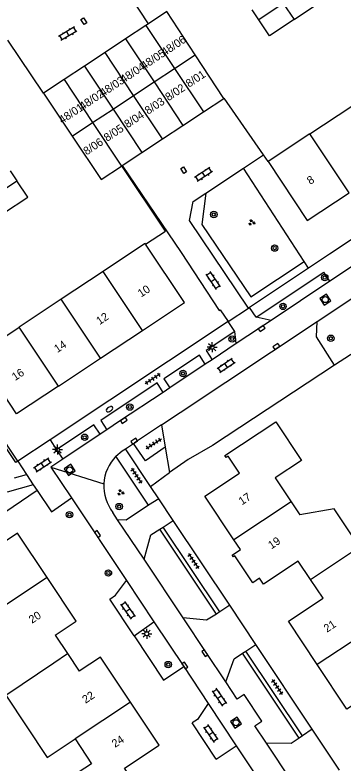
# Model space of a CAD drawing. Extents: x 137999 to 141000, y 397500 to 400501.
# Drawn here: x 138297 to 138337.9, y 399575 to 399668.5 of the extents above; entities that cross this region are included whole.
import ezdxf

# ---------------------------------------------------------------- set-up
doc = ezdxf.new("R2010")
doc.units = 0
for name, color, linetype in [('gg-afsc-erfafscheiding', 7, 'Continuous'), ('gg-anno-huisnummerreeks BGT', 7, 'Continuous'), ('gg-bbg-bijgebouw', 7, 'Continuous'), ('gg-bbg-gedigitaliseerde bebouwing', 7, 'Continuous'), ('gg-bbg-gedigitaliseerde bijgebouw', 7, 'Continuous'), ('gg-bbg-hoofdgebouw', 7, 'Continuous'), ('gg-bbg-tussenscheiding', 7, 'Continuous'), ('gg-knt-verharding', 7, 'Continuous'), ('gg-knt-verharding nz', 7, 'Continuous'), ('gt-grn-groengrens', 7, 'Continuous'), ('gt-grn-weggrens', 7, 'Continuous'), ('gt-symb-boom', 7, 'Continuous'), ('gt-symb-brandkraan', 7, 'Continuous'), ('gt-symb-groenvak', 7, 'Continuous'), ('gt-symb-klinker verharding', 7, 'Continuous'), ('gt-symb-kolk', 7, 'Continuous'), ('gt-symb-kolk center center', 7, 'Continuous'), ('gt-symb-lichtmast', 7, 'Continuous'), ('gt-symb-rioolschacht', 7, 'Continuous'), ('gt-symb-tegel verharding', 7, 'Continuous')]:
    doc.layers.add(name, color=color, linetype=linetype)

# ---------------------------------------------------------------- blocks, each defined once
blk = doc.blocks.new('gt0-RS')
at = {"layer": 'gt-symb-rioolschacht'}
blk.add_lwpolyline([(-0.5, -0.5), (0.5, -0.5), (0.5, 0.5), (-0.5, 0.5)], close=True, dxfattribs=at)
blk.add_circle((0, 0), 0.375, dxfattribs=at)
blk = doc.blocks.new('gt0-KL1')
at = {"layer": 'gt-symb-klinker verharding'}
for p, q in [((-1.15, 0.3), (1.15, 0.3)), ((-1, -0.3), (-1, 0.3)), ((-0.5, 0.3), (-0.5, 0.45)), ((0, -0.3), (0, 0.3)), ((0.5, 0.3), (0.5, 0.45)), ((1, -0.3), (1, 0.3)), ((-1.15, -0.3), (1.15, -0.3)), ((-0.5, -0.45), (-0.5, -0.3)), ((0.5, -0.45), (0.5, -0.3))]:
    blk.add_line(p, q, dxfattribs=at)
blk = doc.blocks.new('gt0-LMAST')
at = {"layer": 'gt-symb-lichtmast'}
for p, q in [((-0.182, 0.173), (-0.447, 0.438)), ((-0.005, 0.246), (-0.005, 0.621)), ((0.172, 0.173), (0.437, 0.438)), ((-0.255, -0.004), (-0.63, -0.004)), ((-0.182, -0.181), (-0.447, -0.446)), ((-0.005, -0.254), (-0.005, -0.629)), ((0.437, -0.446), (0.172, -0.181)), ((0.245, -0.004), (0.62, -0.004))]:
    blk.add_line(p, q, dxfattribs=at)
blk.add_circle((-0.005, -0.004), 0.25, dxfattribs=at)
blk = doc.blocks.new('gt0-BOOM')
at = {"layer": 'gt-symb-boom'}
for radius in [0.4, 0.2]:
    blk.add_circle((0, 0), radius, dxfattribs=at)
blk = doc.blocks.new('gt0-TEG1')
at = {"layer": 'gt-symb-tegel verharding'}
for p, q in [((-1.125, 0), (1.125, 0)), ((-0.9, -0.25), (-0.9, 0.25)), ((-0.45, -0.25), (-0.45, 0.25)), ((0, -0.25), (0, 0.25)), ((0.45, -0.25), (0.45, 0.25)), ((0.9, -0.25), (0.9, 0.25))]:
    blk.add_line(p, q, dxfattribs=at)
blk = doc.blocks.new('gt0-KOLK')
at = {"layer": 'gt-symb-kolk'}
blk.add_lwpolyline([(0, 0), (0.375, 0), (0.375, 0.4), (-0.375, 0.4), (-0.375, 0), (0, 0)], dxfattribs=at)
blk = doc.blocks.new('gt0-KOLKCC')
at = {"layer": 'gt-symb-kolk center center'}
blk.add_lwpolyline([(-0.375, 0.2), (0.375, 0.2), (0.375, -0.2), (-0.375, -0.2)], close=True, dxfattribs=at)
blk = doc.blocks.new('gt0-GRVAK')
at = {"layer": 'gt-symb-groenvak'}
for p, q in [((-0.11, 0.189), (-0.228, 0.24)), ((-0.182, 0.153), (0.088, 0.153)), ((-0.091, 0.211), (-0.156, 0.322)), ((-0.047, 0.214), (-0.047, 0.393)), ((-0.004, 0.211), (0.061, 0.322)), ((0.015, 0.189), (0.133, 0.24)), ((0.262, -0.052), (0.197, 0.059)), ((0.305, -0.049), (0.305, 0.13)), ((0.349, -0.052), (0.414, 0.059)), ((-0.245, -0.228), (-0.363, -0.177)), ((-0.318, -0.264), (-0.047, -0.264)), ((-0.226, -0.206), (-0.291, -0.095)), ((-0.183, -0.203), (-0.183, -0.024)), ((-0.139, -0.206), (-0.074, -0.095)), ((-0.12, -0.228), (-0.002, -0.177)), ((0.243, -0.074), (0.125, -0.023)), ((0.17, -0.11), (0.441, -0.11)), ((0.368, -0.074), (0.486, -0.023))]:
    blk.add_line(p, q, dxfattribs=at)
blk = doc.blocks.new('gt0-BR')
at = {"layer": 'gt-symb-brandkraan'}
for centre, radius, start, end in [((-0.244, 0), 0.206, 107.56694, 252.43307), ((0.599, -2.664), 3, 106.89205, 107.56694), ((0, -0.691), 0.938, 73.10799, 106.89205), ((-0.599, -2.664), 3, 72.43309, 73.10799), ((0.244, 0), 0.206, 287.56695, 72.43309), ((0.599, 2.664), 3, 252.43307, 253.10797), ((0, 0.691), 0.938, 253.10797, 286.89206), ((-0.599, 2.664), 3, 286.89206, 287.56695)]:
    blk.add_arc(centre, radius, start, end, dxfattribs=at)

msp = doc.modelspace()

# ---------------------------------------------------------------- linework, layer by layer
at = {"layer": 'gg-afsc-erfafscheiding'}
for p, q in [((138313.661, 399667.342), (138308.575, 399675.225)), ((138327.43, 399667.857), (138326.596, 399669.102)), ((138300.604, 399658.7), (138296.142, 399665.293)), ((138328.58, 399650.16), (138328.018, 399650.974)), ((138296.438, 399648.991), (138297.27, 399647.743)), ((138297.402, 399612.731), (138284.82, 399631.59)), ((138343.575, 399629.136), (138336.884, 399624.719)), ((138299.793, 399609.056), (138291.36, 399603.341)), ((138322.132, 399575.534), (138319.133, 399580.038))]:
    msp.add_line(p, q, dxfattribs=at)
for points in [[(138328.018, 399650.974), (138323.122, 399658.068), (138323.073, 399658.036)], [(138313.32, 399639.82), (138315.806, 399641.472), (138310.366, 399649.617)]]:
    msp.add_lwpolyline(points, dxfattribs=at)
at = {"layer": 'gg-bbg-bijgebouw'}
for p, q in [((138313.365, 399667.146), (138310.811, 399665.456)), ((138313.661, 399667.342), (138313.365, 399667.146)), ((138310.811, 399665.456), (138308.26, 399663.768)), ((138308.26, 399663.768), (138305.706, 399662.077)), ((138323.073, 399658.036), (138319.498, 399663.487)), ((138305.706, 399662.077), (138303.153, 399660.387)), ((138303.153, 399660.387), (138300.604, 399658.7)), ((138300.604, 399658.7), (138304.162, 399653.327)), ((138320.521, 399656.345), (138323.073, 399658.036)), ((138317.969, 399654.654), (138320.521, 399656.345)), ((138315.418, 399652.964), (138317.969, 399654.654)), ((138304.162, 399653.327), (138307.761, 399647.891)), ((138312.864, 399651.272), (138315.418, 399652.964)), ((138310.417, 399649.651), (138312.864, 399651.272)), ((138307.761, 399647.891), (138310.312, 399649.581)), ((138310.312, 399649.581), (138310.366, 399649.617)), ((138310.366, 399649.617), (138310.417, 399649.651))]:
    msp.add_line(p, q, dxfattribs=at)
msp.add_lwpolyline([(138319.498, 399663.487), (138315.968, 399668.869), (138313.661, 399667.342)], dxfattribs=at)
at = {"layer": 'gg-bbg-gedigitaliseerde bebouwing'}
for p, q in [((138331.476, 399607.641), (138332.54, 399606.04)), ((138336.822, 399606.758), (138332.54, 399606.04)), ((138339.978, 399602.034), (138336.822, 399606.758)), ((138302.038, 399591), (138303.583, 399588.699)), ((138303.583, 399588.699), (138305.056, 399586.505))]:
    msp.add_line(p, q, dxfattribs=at)
for points in [[(138329.55, 399617.651), (138332.765, 399612.821), (138329.483, 399610.638), (138331.476, 399607.641)], [(138295.875, 399583.524), (138301.048, 399575.724), (138304.527, 399578.045)], [(138304.527, 399578.045), (138306.581, 399574.947), (138303.143, 399572.668), (138306.226, 399568.018)]]:
    msp.add_lwpolyline(points, dxfattribs=at)
at = {"layer": 'gg-bbg-gedigitaliseerde bijgebouw'}
for p, q in [((138330.475, 399669.888), (138327.43, 399667.857)), ((138294.239, 399645.721), (138297.27, 399647.743))]:
    msp.add_line(p, q, dxfattribs=at)
for points in [[(138331.817, 399667.88), (138334.86, 399669.91), (138333.52, 399671.92)], [(138331.817, 399667.88), (138328.773, 399665.849), (138327.43, 399667.857)], [(138295.594, 399643.688), (138298.626, 399645.711), (138297.27, 399647.743)]]:
    msp.add_lwpolyline(points, dxfattribs=at)
at = {"layer": 'gg-bbg-hoofdgebouw'}
for p, q in [((138333.804, 399653.62), (138339.032, 399657.081)), ((138333.804, 399653.62), (138328.58, 399650.16)), ((138328.58, 399650.16), (138333.47, 399642.78)), ((138333.47, 399642.78), (138338.695, 399646.245)), ((138313.185, 399639.86), (138308.022, 399636.431)), ((138308.022, 399636.431), (138302.791, 399632.956)), ((138302.791, 399632.956), (138297.559, 399629.48)), ((138307.684, 399625.584), (138312.917, 399629.057)), ((138302.451, 399622.111), (138307.684, 399625.584)), ((138325.127, 399601.698), (138324.321, 399602.906))]:
    msp.add_line(p, q, dxfattribs=at)
for points in [[(138312.917, 399629.057), (138318.15, 399632.53), (138313.32, 399639.82)], [(138313.32, 399639.82), (138313.26, 399639.91), (138313.185, 399639.86)], [(138302.451, 399622.111), (138297.22, 399618.64), (138292.35, 399626.02), (138297.559, 399629.48)], [(138324.321, 399602.906), (138320.69, 399608.35), (138325.01, 399611.24), (138323.59, 399613.37), (138323.34, 399613.2), (138323.2, 399613.42), (138329.55, 399617.651)], [(138301.037, 399598.217), (138297.36, 399603.74), (138293.03, 399600.85), (138291.36, 399603.341)], [(138327.524, 399598.103), (138326.677, 399597.538), (138324.441, 399600.89), (138324.257, 399600.767), (138324.094, 399601.009), (138325.127, 399601.698)], [(138333.874, 399597.957), (138332.35, 399600.24), (138328.02, 399597.36), (138327.524, 399598.103)], [(138302.038, 399591), (138304.67, 399592.76), (138301.037, 399598.217)], [(138334.69, 399587.345), (138331.11, 399592.73), (138335.44, 399595.61), (138333.874, 399597.957)], [(138311.427, 399582.648), (138307.68, 399588.26), (138305.056, 399586.505)], [(138344.312, 399582.284), (138342.74, 399584.63), (138338.41, 399581.75), (138334.69, 399587.345)], [(138312.256, 399572.027), (138310.69, 399574.39), (138315.01, 399577.28), (138311.427, 399582.648)]]:
    msp.add_lwpolyline(points, dxfattribs=at)
at = {"layer": 'gg-bbg-tussenscheiding'}
for p, q in [((138330.475, 399669.888), (138331.817, 399667.88)), ((138313.365, 399667.146), (138316.921, 399661.779)), ((138310.811, 399665.456), (138314.368, 399660.088)), ((138311.818, 399658.398), (138308.26, 399663.768)), ((138316.921, 399661.779), (138319.498, 399663.487)), ((138305.706, 399662.077), (138309.264, 399656.706)), ((138314.368, 399660.088), (138316.921, 399661.779)), ((138316.921, 399661.779), (138320.521, 399656.345)), ((138303.153, 399660.387), (138306.711, 399655.016)), ((138311.818, 399658.398), (138314.368, 399660.088)), ((138314.368, 399660.088), (138317.969, 399654.654)), ((138309.264, 399656.706), (138311.818, 399658.398)), ((138315.418, 399652.964), (138311.818, 399658.398)), ((138306.711, 399655.016), (138309.264, 399656.706)), ((138309.264, 399656.706), (138312.864, 399651.272)), ((138304.162, 399653.327), (138306.711, 399655.016)), ((138306.711, 399655.016), (138310.312, 399649.581)), ((138338.695, 399646.245), (138333.804, 399653.62)), ((138312.917, 399629.057), (138308.022, 399636.431)), ((138307.684, 399625.584), (138302.791, 399632.956)), ((138302.451, 399622.111), (138297.559, 399629.48)), ((138331.476, 399607.641), (138324.321, 399602.906)), ((138333.874, 399597.957), (138339.978, 399602.034)), ((138301.037, 399598.217), (138294.121, 399593.592)), ((138341.729, 399591.976), (138334.69, 399587.345)), ((138301.893, 399587.564), (138303.583, 399588.699)), ((138295.875, 399583.524), (138301.893, 399587.564)), ((138311.427, 399582.648), (138304.527, 399578.045))]:
    msp.add_line(p, q, dxfattribs=at)
at = {"layer": 'gg-knt-verharding'}
for p, q in [((138325.505, 399649.302), (138328.018, 399650.974)), ((138310.417, 399649.651), (138317.731, 399638.79)), ((138320.833, 399646.194), (138325.505, 399649.302)), ((138333.066, 399637.651), (138325.505, 399649.302)), ((138319.247, 399645.139), (138320.833, 399646.194)), ((138318.789, 399642.787), (138319.247, 399645.139)), ((138326.151, 399631.856), (138318.789, 399642.787)), ((138333.608, 399636.816), (138333.066, 399637.651)), ((138333.608, 399636.816), (138326.26, 399631.928)), ((138339.112, 399637.078), (138336.29, 399635.195)), ((138327.109, 399630.7), (138335.537, 399636.323)), ((138336.29, 399635.195), (138335.537, 399636.323)), ((138336.29, 399635.195), (138328.951, 399630.299)), ((138334.711, 399630.191), (138340.363, 399633.957)), ((138326.26, 399631.928), (138326.151, 399631.856)), ((138327.109, 399630.7), (138326.26, 399631.928)), ((138323.614, 399630.168), (138301.412, 399615.399)), ((138324.45, 399628.908), (138323.614, 399630.168)), ((138328.951, 399630.299), (138324.614, 399627.406)), ((138328.951, 399630.299), (138327.109, 399630.7)), ((138324.614, 399627.406), (138324.45, 399628.908)), ((138324.614, 399627.406), (138321.609, 399625.402)), ((138320.748, 399624.827), (138316.329, 399621.879)), ((138321.609, 399625.402), (138320.748, 399624.827)), ((138316.329, 399621.879), (138315.491, 399621.32)), ((138315.491, 399621.32), (138310.078, 399617.709)), ((138310.078, 399617.709), (138308.484, 399616.646)), ((138315.303, 399617.266), (138311.916, 399615.009)), ((138315.303, 399617.266), (138315.771, 399614.478)), ((138307.648, 399616.088), (138302.983, 399612.976)), ((138308.484, 399616.646), (138307.648, 399616.088)), ((138301.412, 399615.399), (138297.402, 399612.731)), ((138301.412, 399615.399), (138302.219, 399614.155)), ((138310.807, 399614.271), (138311.799, 399614.931)), ((138313.94, 399609.561), (138310.807, 399614.271)), ((138311.799, 399614.931), (138311.916, 399615.009)), ((138315.771, 399614.478), (138316.299, 399611.331)), ((138302.219, 399614.155), (138302.983, 399612.976)), ((138313.697, 399607.215), (138309.618, 399613.342)), ((138297.402, 399612.731), (138298.47, 399611.077)), ((138302.983, 399612.976), (138301.52, 399612)), ((138301.52, 399612), (138304.088, 399608.132)), ((138298.47, 399611.077), (138299.32, 399609.76)), ((138299.32, 399609.76), (138296.061, 399608.844)), ((138299.32, 399609.76), (138299.793, 399609.056)), ((138314.956, 399608.033), (138313.94, 399609.561)), ((138304.088, 399608.132), (138310.92, 399597.84)), ((138314.956, 399608.033), (138313.697, 399607.215)), ((138316.76, 399605.322), (138314.956, 399608.033)), ((138309.824, 399605.403), (138309.24, 399606.33)), ((138315.504, 399604.498), (138316.76, 399605.322)), ((138323.802, 399594.735), (138316.76, 399605.322)), ((138315.086, 399604.223), (138315.504, 399604.498)), ((138322.559, 399593.899), (138315.504, 399604.498)), ((138317.996, 399593.149), (138313.127, 399600.492)), ((138310.92, 399597.84), (138314.343, 399592.684)), ((138323.802, 399594.735), (138322.559, 399593.899)), ((138327.06, 399589.836), (138323.802, 399594.735)), ((138322.317, 399593.736), (138322.144, 399593.62)), ((138322.559, 399593.899), (138322.317, 399593.736)), ((138311.894, 399590.908), (138314.343, 399592.684)), ((138314.343, 399592.684), (138318.069, 399587.071)), ((138325.395, 399588.737), (138325.812, 399589.012)), ((138325.812, 399589.012), (138327.06, 399589.836)), ((138332.855, 399578.43), (138325.812, 399589.012)), ((138334.091, 399579.266), (138327.06, 399589.836)), ((138318.069, 399587.071), (138321.137, 399582.449)), ((138321.137, 399582.449), (138324.622, 399577.2)), ((138334.091, 399579.266), (138332.855, 399578.43)), ((138337.49, 399574.155), (138334.091, 399579.266)), ((138332.855, 399578.43), (138332.441, 399578.15)), ((138322.132, 399575.534), (138324.622, 399577.2)), ((138324.622, 399577.2), (138331.691, 399566.551))]:
    msp.add_line(p, q, dxfattribs=at)
for points in [[(138357.133, 399652.465), (138336.262, 399638.582), (138333.608, 399636.816)], [(138297.402, 399612.731), (138297.16, 399612.57), (138284.58, 399631.42), (138284.82, 399631.59)], [(138322.501, 399631.546), (138322.632, 399631.633), (138323.614, 399630.168)], [(138336.884, 399624.719), (138334.635, 399628.241), (138334.711, 399630.191)], [(138324.45, 399628.908), (138320.868, 399626.531), (138321.609, 399625.402)], [(138320.748, 399624.827), (138320.028, 399625.965), (138315.581, 399623.02), (138316.329, 399621.879)], [(138336.884, 399624.719), (138321.672, 399614.675), (138318.628, 399612.937), (138316.299, 399611.331)], [(138315.491, 399621.32), (138314.77, 399622.493), (138307.722, 399617.814), (138308.484, 399616.646)], [(138307.648, 399616.088), (138306.863, 399617.282), (138302.219, 399614.155)], [(138309.618, 399613.342), (138310.399, 399614), (138310.807, 399614.271)], [(138315.771, 399614.478), (138313.319, 399612.76), (138311.799, 399614.931)], [(138299.793, 399609.056), (138301.57, 399606.41), (138304.088, 399608.132)], [(138313.697, 399607.215), (138310.894, 399605.363), (138309.824, 399605.403)], [(138313.127, 399600.492), (138313.973, 399603.518), (138315.086, 399604.223)], [(138311.894, 399590.908), (138308.84, 399595.494), (138309.56, 399596.003), (138310.92, 399597.84)], [(138322.144, 399593.62), (138320.908, 399592.859), (138317.996, 399593.149)], [(138323.319, 399585.169), (138324.341, 399588.055), (138325.395, 399588.737)], [(138328.375, 399577.523), (138326.938, 399579.682), (138327.797, 399580.262), (138325.591, 399583.606), (138324.718, 399583.019), (138323.319, 399585.169)], [(138321.137, 399582.449), (138319.797, 399580.482), (138319.133, 399580.038)], [(138332.441, 399578.15), (138331.447, 399577.459), (138328.375, 399577.523)]]:
    msp.add_lwpolyline(points, dxfattribs=at)
for centre, radius, start, end in [((138313.418, 399609.62), 5.319, 135.60054, 176.91165), ((138313.417, 399609.621), 5.318, 176.91816, 218.23261)]:
    msp.add_arc(centre, radius, start, end, dxfattribs=at)
at = {"layer": 'gg-knt-verharding nz'}
for p, q in [((138317.731, 399638.79), (138322.501, 399631.546)), ((138317.608, 399618.801), (138334.711, 399630.191)), ((138315.303, 399617.266), (138317.608, 399618.801)), ((138313.127, 399600.492), (138309.824, 399605.403)), ((138333.776, 399569.384), (138328.375, 399577.523))]:
    msp.add_line(p, q, dxfattribs=at)
msp.add_lwpolyline([(138323.319, 399585.169), (138320.853, 399588.855), (138317.996, 399593.149)], dxfattribs=at)
at = {"layer": 'gt-grn-groengrens'}
for p, q in [((138313.94, 399609.561), (138316.299, 399611.331)), ((138322.144, 399593.62), (138315.086, 399604.223)), ((138332.441, 399578.15), (138325.395, 399588.737))]:
    msp.add_line(p, q, dxfattribs=at)
for points in [[(138320.833, 399646.194), (138320.333, 399642.285), (138326.425, 399633.239), (138333.066, 399637.651)], [(138311.894, 399590.908), (138315.561, 399585.401), (138318.069, 399587.071)]]:
    msp.add_lwpolyline(points, dxfattribs=at)
at = {"layer": 'gt-grn-weggrens'}
for p, q in [((138323.614, 399630.168), (138326.151, 399631.856)), ((138301.52, 399612), (138308.107, 399609.907)), ((138296.97, 399610.65), (138298.47, 399611.077))]:
    msp.add_line(p, q, dxfattribs=at)

# ---------------------------------------------------------------- block references
at = {"layer": 'gt-symb-boom'}
for p in [(138321.819, 399643.53), (138329.405, 399639.336), (138335.649, 399635.661), (138330.448, 399632.057), (138324.106, 399627.991), (138317.982, 399623.677), (138311.349, 399619.487), (138305.724, 399615.713), (138310.023, 399607.064), (138303.828, 399606.047), (138308.68, 399598.759), (138316.139, 399587.331)]:
    msp.add_blockref('gt0-BOOM', p, dxfattribs=at)
at = {"layer": 'gt-symb-boom', "rotation": 33.70595654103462}
msp.add_blockref('gt0-BOOM', (138336.41, 399628.078), dxfattribs=at)
at = {"layer": 'gt-symb-brandkraan', "rotation": -146.57996880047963}
msp.add_blockref('gt0-BR', (138308.812, 399619.209), dxfattribs=at)
at = {"layer": 'gt-symb-groenvak'}
for p in [(138326.537, 399642.534), (138310.2, 399608.817)]:
    msp.add_blockref('gt0-GRVAK', p, dxfattribs=at)
at = {"layer": 'gt-symb-klinker verharding'}
for p, rotation in [((138303.605, 399666.113), -149.20328608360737), ((138320.538, 399648.517), -146.91369260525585), ((138321.759, 399635.277), 123.83302869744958), ((138323.35, 399624.692), 34.532124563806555), ((138300.457, 399612.271), 33.83302869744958), ((138311.099, 399594.11), -55.18164551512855), ((138322.496, 399583.261), -55.46787543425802), ((138321.443, 399578.734), -55.46787543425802)]:
    msp.add_blockref('gt0-KL1', p, dxfattribs=dict(at, rotation=rotation))
at = {"layer": 'gt-symb-kolk'}
for p, rotation in [((138327.896, 399629.116), 33.78542795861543), ((138329.725, 399626.872), 33.785427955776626), ((138310.708, 399617.649), 33.785427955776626), ((138312.004, 399615.068), 33.78542795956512), ((138307.146, 399603.522), -56.42118627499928), ((138320.853, 399588.855), 123.79526709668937), ((138318.039, 399587.113), -56.42118627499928)]:
    msp.add_blockref('gt0-KOLK', p, dxfattribs=dict(at, rotation=rotation))
at = {"layer": 'gt-symb-kolk center center'}
for p, rotation in [((138305.629, 399667.685), -56.50059992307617), ((138318.064, 399649.072), 122.0053832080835)]:
    msp.add_blockref('gt0-KOLKCC', p, dxfattribs=dict(at, rotation=rotation))
at = {"layer": 'gt-symb-lichtmast'}
for p in [(138321.616, 399626.964), (138302.337, 399614.173), (138313.468, 399591.19)]:
    msp.add_blockref('gt0-LMAST', p, dxfattribs=at)
at = {"layer": 'gt-symb-rioolschacht'}
for p, rotation in [((138335.713, 399632.9), 33.78542795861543), ((138303.861, 399611.643), 33.78542795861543), ((138324.594, 399580.072), -56.42118627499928)]:
    msp.add_blockref('gt0-RS', p, dxfattribs=dict(at, rotation=rotation))
at = {"layer": 'gt-symb-tegel verharding'}
for p, rotation in [((138314.186, 399623.022), -146.5005999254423), ((138314.337, 399614.925), 31.798912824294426), ((138312.171, 399610.917), -56.500599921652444), ((138319.302, 399600.247), -56.50059992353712), ((138329.728, 399584.526), -56.500599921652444)]:
    msp.add_blockref('gt0-TEG1', p, dxfattribs=dict(at, rotation=rotation))

# ---------------------------------------------------------------- texts
at = {"layer": 'gg-anno-huisnummerreeks BGT'}
for s, rotation, p in [('48/06', 33.5, (138315.681, 399663.283)), ('48/05', 33.5, (138313.115, 399661.584)), ('48/04', 33.5, (138310.563, 399659.895)), ('8/01', 33.5, (138318.73, 399659.358)), ('48/03', 33.5, (138308.01, 399658.206)), ('48/02', 33.5, (138305.457, 399656.515)), ('8/02', 33.5, (138316.178, 399657.667)), ('8/03', 33.5, (138313.626, 399655.977)), ('48/01', 33.5, (138302.906, 399654.827)), ('8/04', 33.5, (138311.074, 399654.286)), ('8/05', 33.5, (138308.521, 399652.594)), ('8/06', 33.5, (138305.969, 399650.904)), ('8', 33.6, (138333.843, 399647.226)), ('10', 33.6, (138312.755, 399633.149)), ('12', 33.6, (138307.578, 399629.713)), ('14', 33.6, (138302.319, 399626.223)), ('16', 33.6, (138297.057, 399622.731)), ('17', 33.7, (138325.33, 399607.201)), ('19', 33.7, (138328.998, 399601.702)), ('20', 33.7, (138299.165, 399592.41)), ('21', 33.6, (138335.93, 399591.302)), ('22', 33.7, (138305.83, 399582.428)), ('24', 33.7, (138309.512, 399576.912))]:
    msp.add_text(s, height=1, rotation=rotation, dxfattribs=at).set_placement(p)

doc.saveas('drawing.dxf')
